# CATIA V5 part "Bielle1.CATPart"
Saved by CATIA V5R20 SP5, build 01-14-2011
Part number: Bielle1
Bounding box of the stored display mesh (mm): x 0 to 20, y -9.982 to 69.725, z -77.293 to 9.982
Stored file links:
  E:\IAO_2010\iao\IAO_MMS_Groupe2\IAO_MMS_Groupe2\flafosse\Catia\IAO\Bielle1.CATPart
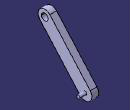
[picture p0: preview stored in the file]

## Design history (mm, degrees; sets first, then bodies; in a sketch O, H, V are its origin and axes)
Body1 (main body)
  Point1 "B": stored without definition
  Sketch1 on yz-plane, origin (0, 0, 0), H (0, 1, 0), V (0, 0, 1)
    circle A1 centre (0, 0) radius 5
    arc A2 centre (0, 0) radius 10 from (7.479, 6.6381) to (-7.479, -6.6381) ccw
    arc A3 centre (59.7428, -67.3112) radius 10 from (52.2638, -73.9493) to (67.2219, -60.6731) ccw
    point P1 (59.7428, -67.3112)
    line L1 (67.2219, -60.6731) -> (7.479, 6.6381)
    line L2 (52.2638, -73.9493) -> (-7.479, -6.6381)
    radius A1 = 5
    radius A2 = 10
    radius A3 = 10
    distance P1 O = 90
    tangency: L1 A2, L1 A3, L2 A2, L2 A3
  Pad1: profile Sketch1, direction (1, 0, 0), length 10
  Point2 "B": stored without definition
  Sketch2 on end face of Pad1, origin (10, 0, 0), H (0, 1, 0), V (0, 0, 1)
    circle A1 centre (59.7428, -67.3112) radius 2.5
    point P1 (59.7428, -67.3112)
    reference projected arc E1 centre (59.7428, -67.3112) radius 10 from (52.2638, -73.9493) to (67.2219, -60.6731) ccw from edge [face of Pad1 from Sketch1.A3 | end face of Pad1]
    radius A1 = 2.5
    distance P1 E1 = 10
  Pad2: profile Sketch2, direction (1, 0, 0), length 10
  Plane1: type Offset, RefPlane yz-plane, Offset 15
  Sketch3 on Plane1, origin (15, 0, 0), H (0, 1, 0), V (0, 0, 1)
    point P1 (59.7428, -67.3112)
    reference projected circle E1 centre (59.7428, -67.3112) radius 2.5 from edge [face of Pad2 from Sketch2.A1 | end face of Pad2]
    concentricity: P1 E1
